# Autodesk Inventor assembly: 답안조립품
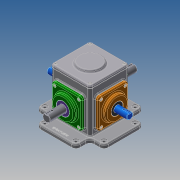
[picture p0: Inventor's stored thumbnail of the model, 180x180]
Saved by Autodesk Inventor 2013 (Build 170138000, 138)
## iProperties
Created: 2019-12
Part Number: 답안조립품
Document SubType Name: Assembly
Designer: Administrator
Mass: 3483.74 g
Surface Area: 3365.09 cm^2
Volume: 1062.39 cm^3
Density: 3.27916 g/cm^3
Author: Administrator
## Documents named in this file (16)
- C:\Users\Administrator\Desktop\391204V1017\답안조립품.iam
- C:\Users\Administrator\Desktop\391204V1017\391204V1017\개스킷.ipt
- C:\Users\Administrator\Desktop\391204V1017\391204V1017\메인베벨기어.ipt
- C:\Users\Administrator\Desktop\391204V1017\391204V1017\메인축.ipt
- C:\Users\Administrator\Desktop\391204V1017\391204V1017\메인커버.ipt
- C:\Users\Administrator\Desktop\391204V1017\391204V1017\베어링 6203.ipt
- C:\Users\Administrator\Desktop\391204V1017\391204V1017\베어링 6204.ipt
- C:\Users\Administrator\Desktop\391204V1017\391204V1017\본체.ipt
- C:\Users\Administrator\Desktop\391204V1017\391204V1017\볼트 M4.ipt
- C:\Users\Administrator\Desktop\391204V1017\391204V1017\상부커버.ipt
- C:\Users\Administrator\Desktop\391204V1017\391204V1017\서브베벨기어.ipt
- C:\Users\Administrator\Desktop\391204V1017\391204V1017\서브축.ipt
- C:\Users\Administrator\Desktop\391204V1017\391204V1017\서브커버.ipt
- C:\Users\Administrator\Desktop\391204V1017\391204V1017\오일 실 17 32 8.ipt
- C:\Users\Administrator\Desktop\391204V1017\391204V1017\오일 실 20 35 8.ipt
- C:\Users\Administrator\Desktop\391204V1017\391204V1017\키 4x4.ipt
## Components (1 placed, 1 different names)
1. 개스킷:1
